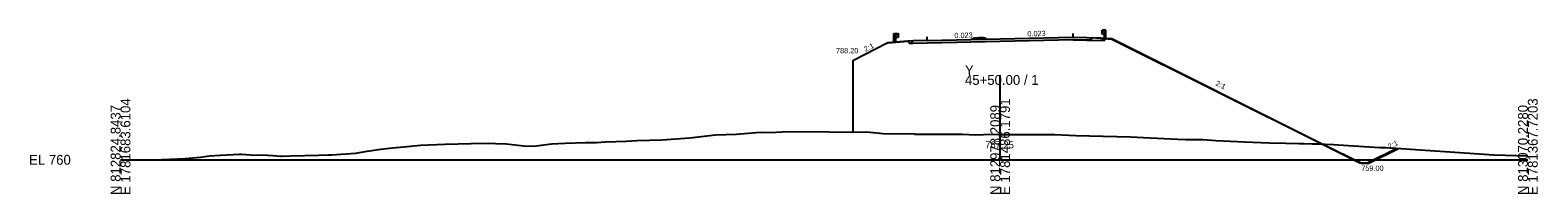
# Model space of a CAD drawing. Extents: x -12583 to 5303, y -44 to 25667.
# Drawn here: x 2874.3 to 3302.8, y 5990.3 to 6036.9 of the extents above; entities that cross this region are included whole.
import ezdxf

# ---------------------------------------------------------------- set-up
doc = ezdxf.new("R2010")
doc.units = 0
for name, color, linetype in [('Exist Cross Section Cell', 7, 'Continuous'), ('Exist XS Center Line Elevation Label', 7, 'Continuous'), ('Exist XS Ground Line', 7, 'Continuous'), ('Prop Conc 5in Monolithic Surface Mount Island', 7, 'Continuous'), ('Prop XS Ditch Standard Text', 7, 'Continuous'), ('Prop XS Dump Level', 7, 'Continuous'), ('Prop XS Earthwork Shape', 7, 'Continuous'), ('Prop XS EOT Tick Mark', 7, 'Continuous'), ('Prop XS Finish Grade', 7, 'Continuous'), ('Prop XS Finish Grade Earthwork', 7, 'Continuous'), ('Prop XS Finish Grade Paved Shoulder', 7, 'Continuous'), ('Prop XS Finish Grade Pavement', 7, 'Continuous'), ('Prop XS Guardrail', 7, 'Continuous'), ('Prop XS Pvmt Edge Slope', 7, 'Continuous'), ('Prop XS SE Text', 7, 'Continuous'), ('Prop XS Side Slope Text', 7, 'Continuous'), ('Prop XS Subgrade Earthwork', 7, 'Continuous')]:
    doc.layers.add(name, color=color, linetype=linetype)

msp = doc.modelspace()

# ---------------------------------------------------------------- linework, layer by layer
at = {"layer": 'Exist Cross Section Cell'}
for p, q in [((3150, 6000), (3150, 6024.13)), ((2900, 6000), (3150, 6000)), ((3150, 6000), (3300, 6000))]:
    msp.add_line(p, q, dxfattribs=at)
at = {"layer": 'Exist XS Ground Line'}
for p, q in [((3088.14, 6007.99), (3096.72, 6008.04)), ((3096.72, 6008.04), (3101.39, 6007.97)), ((2980.53, 6003.71), (2985.22, 6004.18)), ((2985.22, 6004.18), (2992.13, 6004.48)), ((2992.13, 6004.48), (2999.7, 6004.64)), ((2999.7, 6004.64), (3004.72, 6004.73)), ((3004.72, 6004.73), (3006.61, 6004.67)), ((3006.61, 6004.67), (3009.72, 6004.55)), ((3009.72, 6004.55), (3012.96, 6004.17)), ((3012.96, 6004.17), (3015.41, 6003.89)), ((3015.41, 6003.89), (3018.14, 6004.02)), ((3018.14, 6004.02), (3022.47, 6004.52)), ((3022.47, 6004.52), (3026.41, 6004.78)), ((3026.41, 6004.78), (3032.18, 6004.92)), ((3032.18, 6004.92), (3035.3, 6004.9)), ((3035.3, 6004.9), (3037.85, 6005.09)), ((3037.85, 6005.09), (3043.7, 6005.26)), ((3043.7, 6005.26), (3046.72, 6005.48)), ((3046.72, 6005.48), (3053.84, 6005.7)), ((3053.84, 6005.7), (3061.78, 6006.29)), ((3061.78, 6006.29), (3069.13, 6007.1)), ((3069.13, 6007.1), (3075.1, 6007.31)), ((3075.1, 6007.31), (3081.79, 6007.85)), ((3081.79, 6007.85), (3084.67, 6007.8)), ((3084.67, 6007.8), (3088.14, 6007.99)), ((3101.39, 6007.97), (3107.81, 6007.9)), ((3107.81, 6007.9), (3112.06, 6007.95)), ((3112.06, 6007.95), (3116.78, 6007.48)), ((3116.78, 6007.48), (3125.62, 6007.35)), ((3125.62, 6007.35), (3125.95, 6007.34)), ((3125.95, 6007.34), (3133.94, 6007.26)), ((3133.94, 6007.26), (3136.42, 6007.27)), ((3136.42, 6007.27), (3139.34, 6007.26)), ((3139.34, 6007.26), (3143.03, 6007.11)), ((3143.03, 6007.11), (3147.65, 6007.26)), ((3147.65, 6007.26), (3150, 6007.25)), ((3150, 6007.25), (3154.2, 6007.25)), ((3154.2, 6007.25), (3165.57, 6007.21)), ((3165.57, 6007.21), (3171.53, 6006.93)), ((3171.53, 6006.93), (3183.16, 6006.6)), ((3183.16, 6006.6), (3187.07, 6006.5)), ((3187.07, 6006.5), (3192.64, 6006.25)), ((3192.64, 6006.25), (3200.5, 6005.89)), ((3200.5, 6005.89), (3202.77, 6005.82)), ((3202.77, 6005.82), (3207.62, 6005.78)), ((3207.62, 6005.78), (3211.36, 6005.54)), ((3211.36, 6005.54), (3219.47, 6005.16)), ((3219.47, 6005.16), (3226.45, 6004.86)), ((3226.45, 6004.86), (3231.22, 6004.72)), ((3231.22, 6004.72), (3242.42, 6004.49)), ((3242.42, 6004.49), (3244.81, 6004.34)), ((3244.81, 6004.34), (3246.06, 6004.28)), ((3246.06, 6004.28), (3257.93, 6003.52)), ((2900, 6000.01), (2900.6, 6000.02)), ((2900.6, 6000.02), (2909.58, 5999.96)), ((2909.58, 5999.96), (2918.35, 6000.35)), ((2918.35, 6000.35), (2922.71, 6000.77)), ((2922.71, 6000.77), (2925.32, 6001.14)), ((2925.32, 6001.14), (2928.4, 6001.36)), ((2928.4, 6001.36), (2933.77, 6001.59)), ((2933.77, 6001.59), (2934.28, 6001.64)), ((2934.28, 6001.64), (2936.91, 6001.41)), ((2936.91, 6001.41), (2941.73, 6001.34)), ((2941.73, 6001.34), (2943.31, 6001.24)), ((2943.31, 6001.24), (2945.6, 6001.04)), ((2945.6, 6001.04), (2945.93, 6001.03)), ((2945.93, 6001.03), (2948.34, 6001.11)), ((2948.34, 6001.11), (2956.32, 6001.29)), ((2956.32, 6001.29), (2959.11, 6001.43)), ((2959.11, 6001.43), (2959.99, 6001.46)), ((2959.99, 6001.46), (2966.92, 6001.92)), ((2966.92, 6001.92), (2970.07, 6002.45)), ((2970.07, 6002.45), (2973.98, 6003.07)), ((2973.98, 6003.07), (2977.29, 6003.44)), ((2977.29, 6003.44), (2980.53, 6003.71)), ((3257.93, 6003.52), (3258.76, 6003.53)), ((3258.76, 6003.53), (3259.38, 6003.47)), ((3259.38, 6003.47), (3259.69, 6003.46)), ((3259.69, 6003.46), (3290.34, 6001.42)), ((3290.34, 6001.42), (3300, 6001.15))]:
    msp.add_line(p, q, dxfattribs=at)
at = {"layer": 'Prop Conc 5in Monolithic Surface Mount Island'}
for p, q in [((3142, 6034.41), (3142.74, 6034.68)), ((3142, 6034.25), (3142, 6034.41)), ((3142.74, 6034.68), (3143.99, 6034.73)), ((3145.24, 6034.74), (3143.99, 6034.73)), ((3146, 6034.5), (3145.24, 6034.74)), ((3146, 6034.34), (3146, 6034.5))]:
    msp.add_line(p, q, dxfattribs=at)
at = {"layer": 'Prop XS Dump Level'}
for p, q in [((3129.25, 6033.95), (3150, 6034.43)), ((3150, 6034.43), (3170.75, 6034.91))]:
    msp.add_line(p, q, dxfattribs=at)
at = {"layer": 'Prop XS Earthwork Shape'}
for points in [[(3129.25, 6033.16), (3125.25, 6033.07), (3124.44, 6033.05), (3123.75, 6033.74), (3118.11, 6033.29), (3108.17, 6028.2), (3108.17, 6007.9), (3112.06, 6007.95), (3116.78, 6007.48), (3125.62, 6007.35), (3125.95, 6007.34), (3133.94, 6007.26), (3136.42, 6007.27), (3139.34, 6007.26), (3143.03, 6007.11), (3147.65, 6007.26), (3150, 6007.25), (3154.2, 6007.25), (3165.57, 6007.21), (3171.53, 6006.93), (3183.16, 6006.6), (3187.07, 6006.5), (3192.64, 6006.25), (3200.5, 6005.89), (3202.77, 6005.82), (3207.62, 6005.78), (3211.36, 6005.54), (3219.47, 6005.16), (3226.45, 6004.86), (3231.22, 6004.72), (3241.26, 6004.51), (3181.75, 6034.27), (3176.25, 6034.71), (3175.56, 6034.02), (3174.75, 6034.04), (3170.75, 6034.12), (3150, 6033.64)], [(3259.38, 6003.47), (3259.69, 6003.46), (3262.79, 6003.26), (3254.29, 5999), (3252.29, 5999), (3241.26, 6004.51), (3242.42, 6004.49), (3244.81, 6004.34), (3246.06, 6004.28), (3257.93, 6003.52), (3258.76, 6003.53)]]:
    msp.add_lwpolyline(points, close=True, dxfattribs=at)
at = {"layer": 'Prop XS EOT Tick Mark'}
for p, q in [((3129.25, 6033.95), (3129.25, 6034.95)), ((3170.75, 6034.91), (3170.75, 6035.91))]:
    msp.add_line(p, q, dxfattribs=at)
at = {"layer": 'Prop XS Finish Grade'}
for p, q in [((3125.25, 6033.86), (3123.75, 6033.74)), ((3178.75, 6034.75), (3180.25, 6034.63))]:
    msp.add_line(p, q, dxfattribs=at)
at = {"layer": 'Prop XS Finish Grade Earthwork'}
for p, q in [((3180.25, 6034.63), (3181.75, 6034.51)), ((3181.75, 6034.51), (3241.77, 6004.5)), ((3118.11, 6033.29), (3108.17, 6028.2)), ((3118.11, 6033.29), (3123.75, 6033.74)), ((3108.17, 6028.2), (3108.17, 6007.9)), ((3241.77, 6004.5), (3252.77, 5999)), ((3254.77, 5999), (3263.22, 6003.23)), ((3252.77, 5999), (3254.77, 5999))]:
    msp.add_line(p, q, dxfattribs=at)
at = {"layer": 'Prop XS Finish Grade Paved Shoulder'}
for p, q in [((3129.25, 6033.95), (3125.25, 6033.86)), ((3170.75, 6034.91), (3178.75, 6034.75))]:
    msp.add_line(p, q, dxfattribs=at)
at = {"layer": 'Prop XS Finish Grade Pavement'}
for p, q in [((3129.25, 6033.95), (3150, 6034.43)), ((3150, 6034.43), (3170.75, 6034.91)), ((3150, 6034.43), (3170.75, 6034.91))]:
    msp.add_line(p, q, dxfattribs=at)
at = {"layer": 'Prop XS Guardrail'}
for p, q in [((3119.79, 6035.92), (3120.29, 6035.92)), ((3119.79, 6033.42), (3119.79, 6035.92)), ((3120.29, 6035.92), (3120.79, 6035.92)), ((3120.29, 6035.92), (3120.29, 6033.42)), ((3120.79, 6034.79), (3120.29, 6034.79)), ((3120.79, 6035.92), (3121.08, 6035.72)), ((3121.08, 6035.6), (3120.79, 6035.4)), ((3120.79, 6035.4), (3120.79, 6035.31)), ((3120.79, 6035.31), (3121.08, 6035.11)), ((3121.08, 6034.99), (3120.79, 6034.79)), ((3121.08, 6035.72), (3121.11, 6035.66)), ((3121.11, 6035.66), (3121.08, 6035.6)), ((3121.08, 6035.11), (3121.11, 6035.05)), ((3121.11, 6035.05), (3121.08, 6034.99)), ((3178.78, 6036.71), (3178.75, 6036.65)), ((3178.75, 6036.65), (3178.78, 6036.59)), ((3178.78, 6036.09), (3178.75, 6036.03)), ((3178.75, 6036.03), (3178.78, 6035.97)), ((3179.07, 6036.91), (3178.78, 6036.71)), ((3178.78, 6036.59), (3179.07, 6036.39)), ((3179.07, 6036.29), (3178.78, 6036.09)), ((3178.78, 6035.97), (3179.07, 6035.77)), ((3179.57, 6036.91), (3179.07, 6036.91)), ((3179.07, 6036.39), (3179.07, 6036.29)), ((3179.07, 6035.77), (3179.57, 6035.77)), ((3180.07, 6036.91), (3179.57, 6036.91)), ((3179.57, 6036.91), (3179.57, 6034.41)), ((3180.07, 6034.41), (3180.07, 6036.91))]:
    msp.add_line(p, q, dxfattribs=at)
at = {"layer": 'Prop XS Pvmt Edge Slope'}
for p, q in [((3125.25, 6033.86), (3124.44, 6033.05)), ((3178.75, 6034.75), (3179.56, 6033.94))]:
    msp.add_line(p, q, dxfattribs=at)
at = {"layer": 'Prop XS Subgrade Earthwork'}
for p, q in [((3170.75, 6034.12), (3150, 6033.64)), ((3170.75, 6034.12), (3174.75, 6034.04)), ((3174.75, 6034.04), (3179.56, 6033.94)), ((3179.56, 6033.94), (3180.25, 6034.63)), ((3124.44, 6033.05), (3123.75, 6033.74)), ((3125.25, 6033.07), (3124.44, 6033.05)), ((3129.25, 6033.16), (3125.25, 6033.07)), ((3150, 6033.64), (3129.25, 6033.16))]:
    msp.add_line(p, q, dxfattribs=at)

# ---------------------------------------------------------------- texts
at = {"layer": 'Exist Cross Section Cell'}
for s, p in [('Y', (3140, 6024.13)), ('45+50.00 / 1', (3140, 6021.33)), ('EL 760', (2874, 5998.6))]:
    msp.add_text(s, height=2.8, dxfattribs=at).set_placement(p)
for s, p in [('E 1781683.6104', (2902.8, 5990)), ('E 1781486.1791', (3152.8, 5990)), ('E 1781367.7203', (3302.8, 5990)), ('N 812824.8437', (2900, 5990)), ('N 812978.2089', (3150, 5990)), ('N 813070.2280', (3300, 5990))]:
    msp.add_text(s, height=2.8, rotation=90, dxfattribs=at).set_placement(p)
at = {"layer": 'Exist XS Center Line Elevation Label'}
msp.add_text('767.25', height=2, dxfattribs=at).set_placement((3145.74, 6003.25))
at = {"layer": 'Prop XS Ditch Standard Text'}
for s, p in [('788.20', (3103.36, 6030.32)), ('759.00', (3252.66, 5996.86))]:
    msp.add_text(s, height=1.5, dxfattribs=at).set_placement(p)
at = {"layer": 'Prop XS Dump Level'}
for p in [(3178.75, 6034.47), (3121.25, 6033.5)]:
    msp.add_text('Case2', height=0.04, dxfattribs=at).set_placement(p)
at = {"layer": 'Prop XS SE Text'}
for rotation, p in [(1.3276, (3137.03, 6034.63)), (1.3287, (3157.78, 6035.11)), (1.3287, (3157.78, 6035.11))]:
    msp.add_text('0.023', height=1.5, rotation=rotation, dxfattribs=at).set_placement(p)
at = {"layer": 'Prop XS Side Slope Text'}
for rotation, p in [(26.5651, (3111.75, 6030.69)), (333.4349, (3211.09, 6021.28)), (26.5651, (3260.69, 6003))]:
    msp.add_text('2:1', height=1.5, rotation=rotation, dxfattribs=at).set_placement(p)

doc.saveas('drawing.dxf')
